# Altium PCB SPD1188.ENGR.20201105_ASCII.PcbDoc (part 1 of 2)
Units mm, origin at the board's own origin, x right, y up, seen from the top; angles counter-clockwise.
Board outline 110.11 x 115.1 mm, 2 copper layers (Top Layer, Bottom Layer); 167 components, 110 nets, 467 pads, 496 vias.
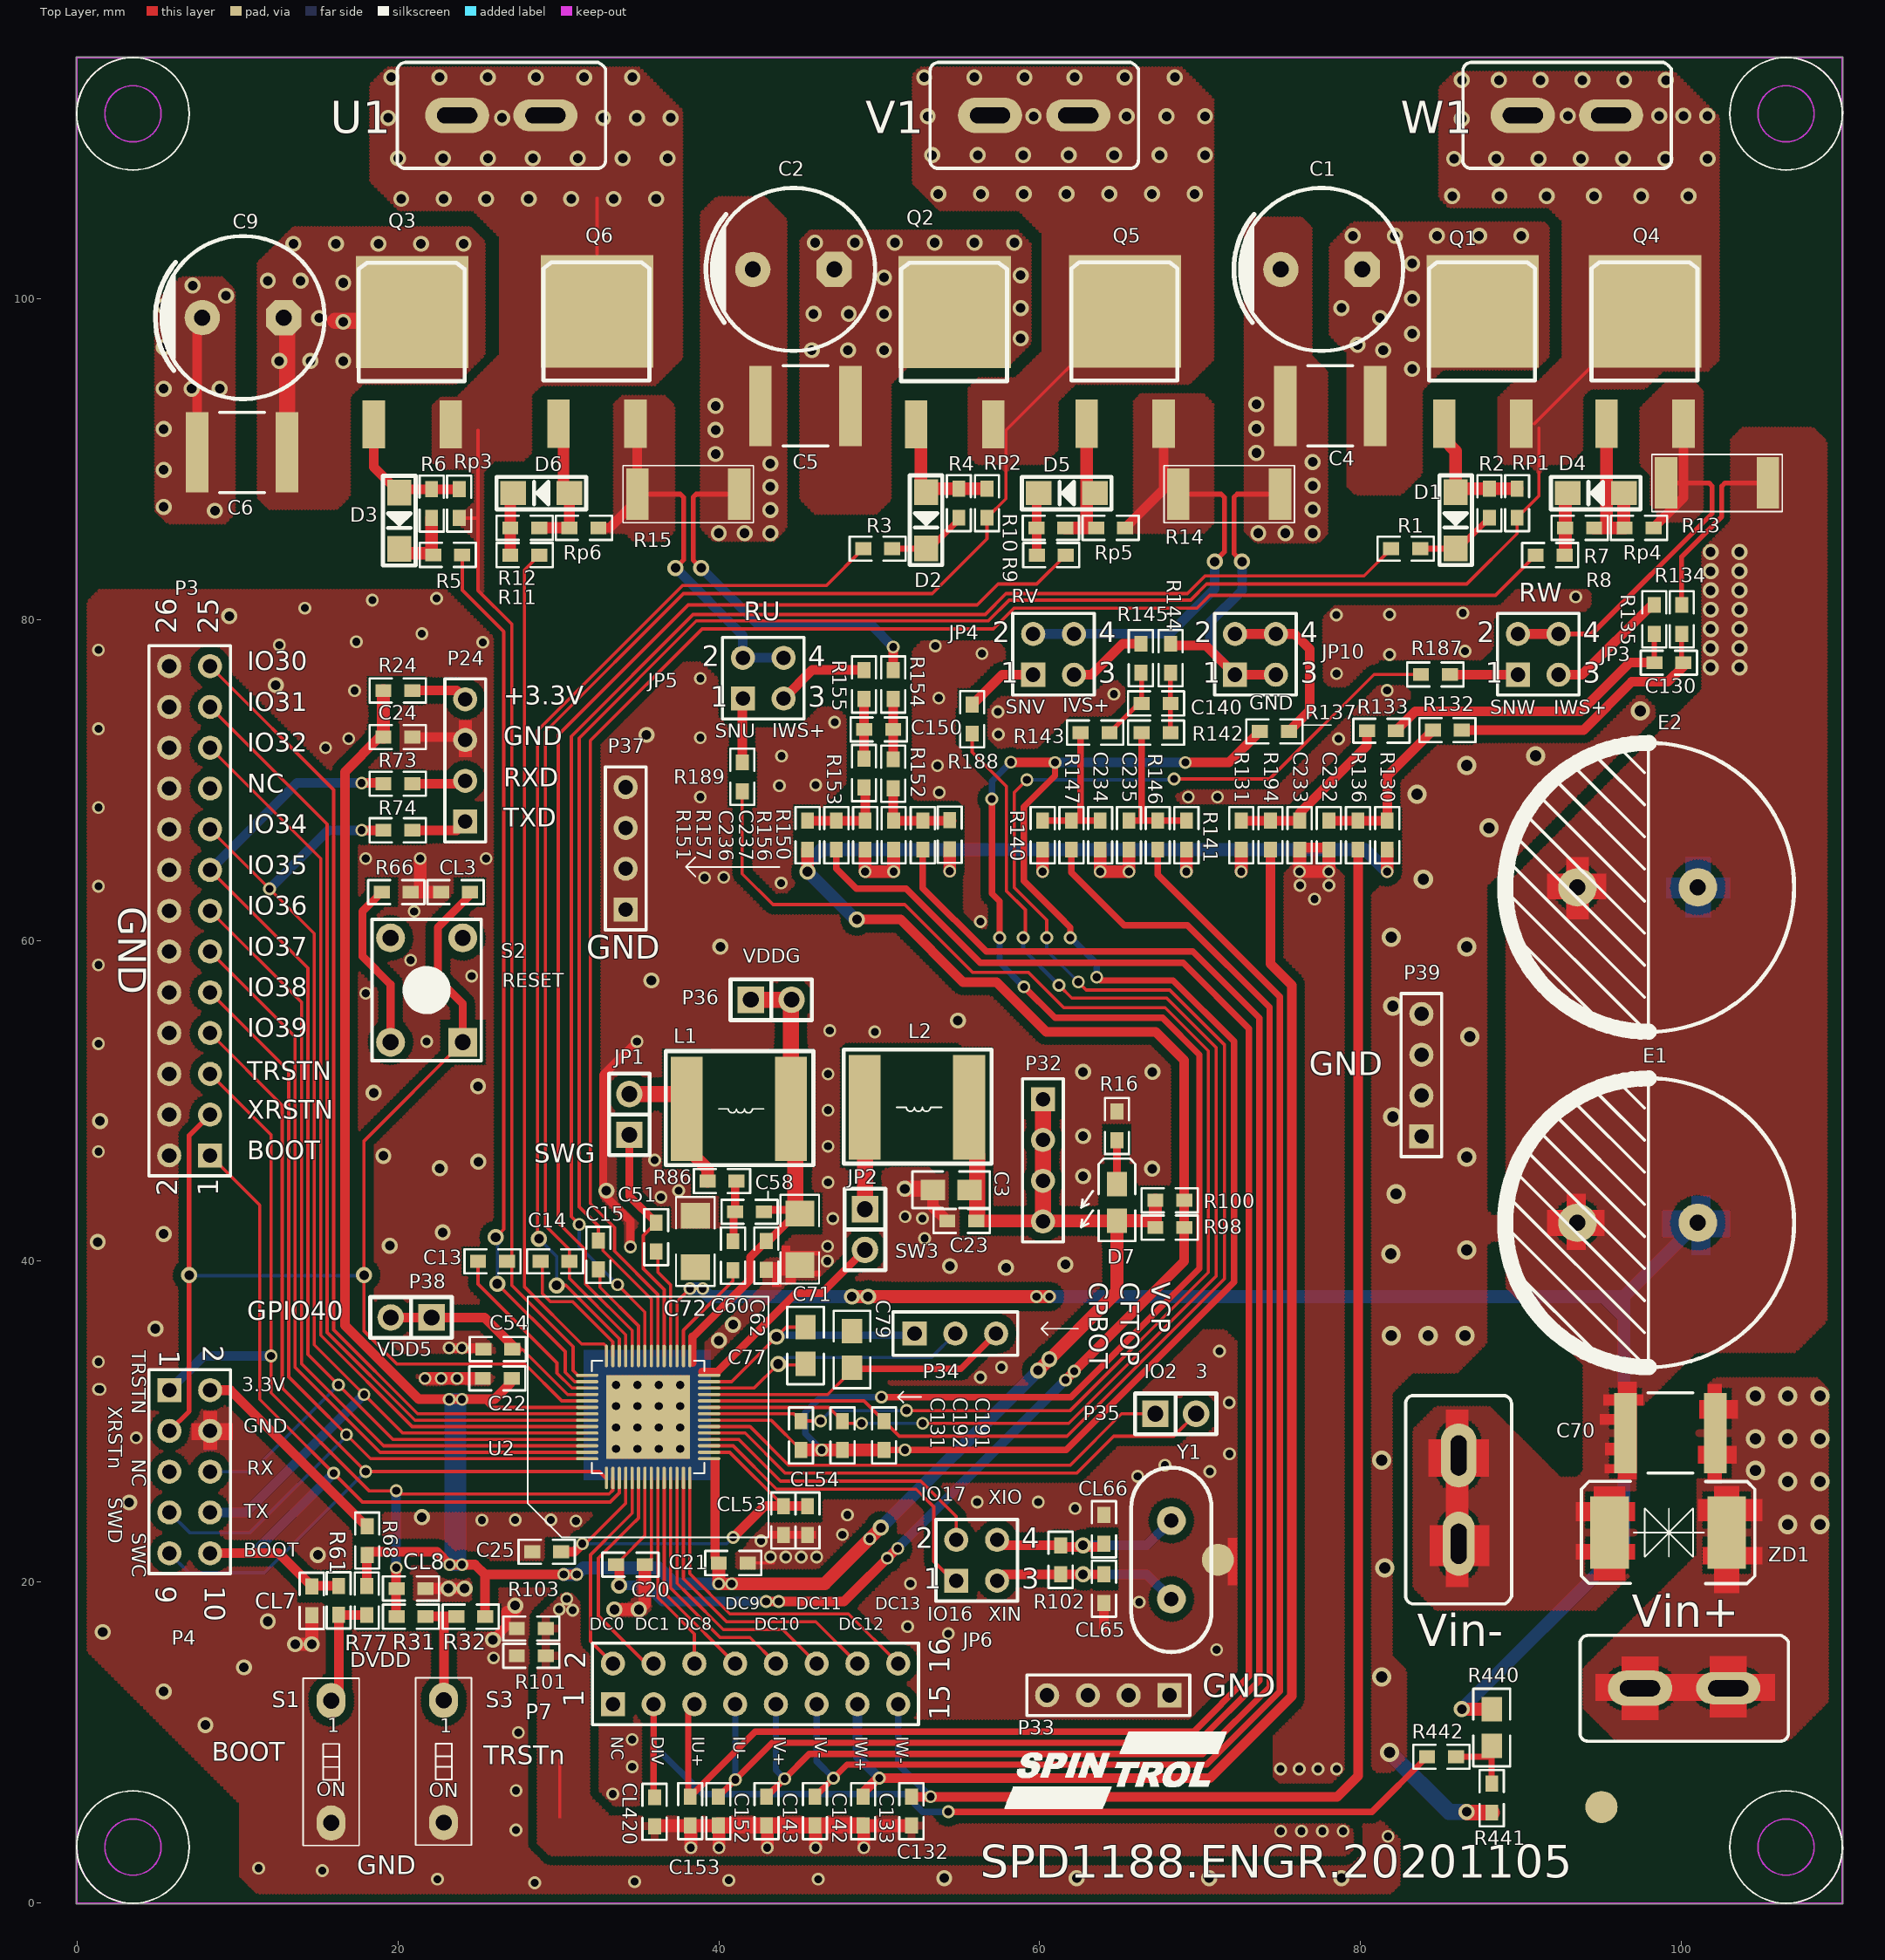
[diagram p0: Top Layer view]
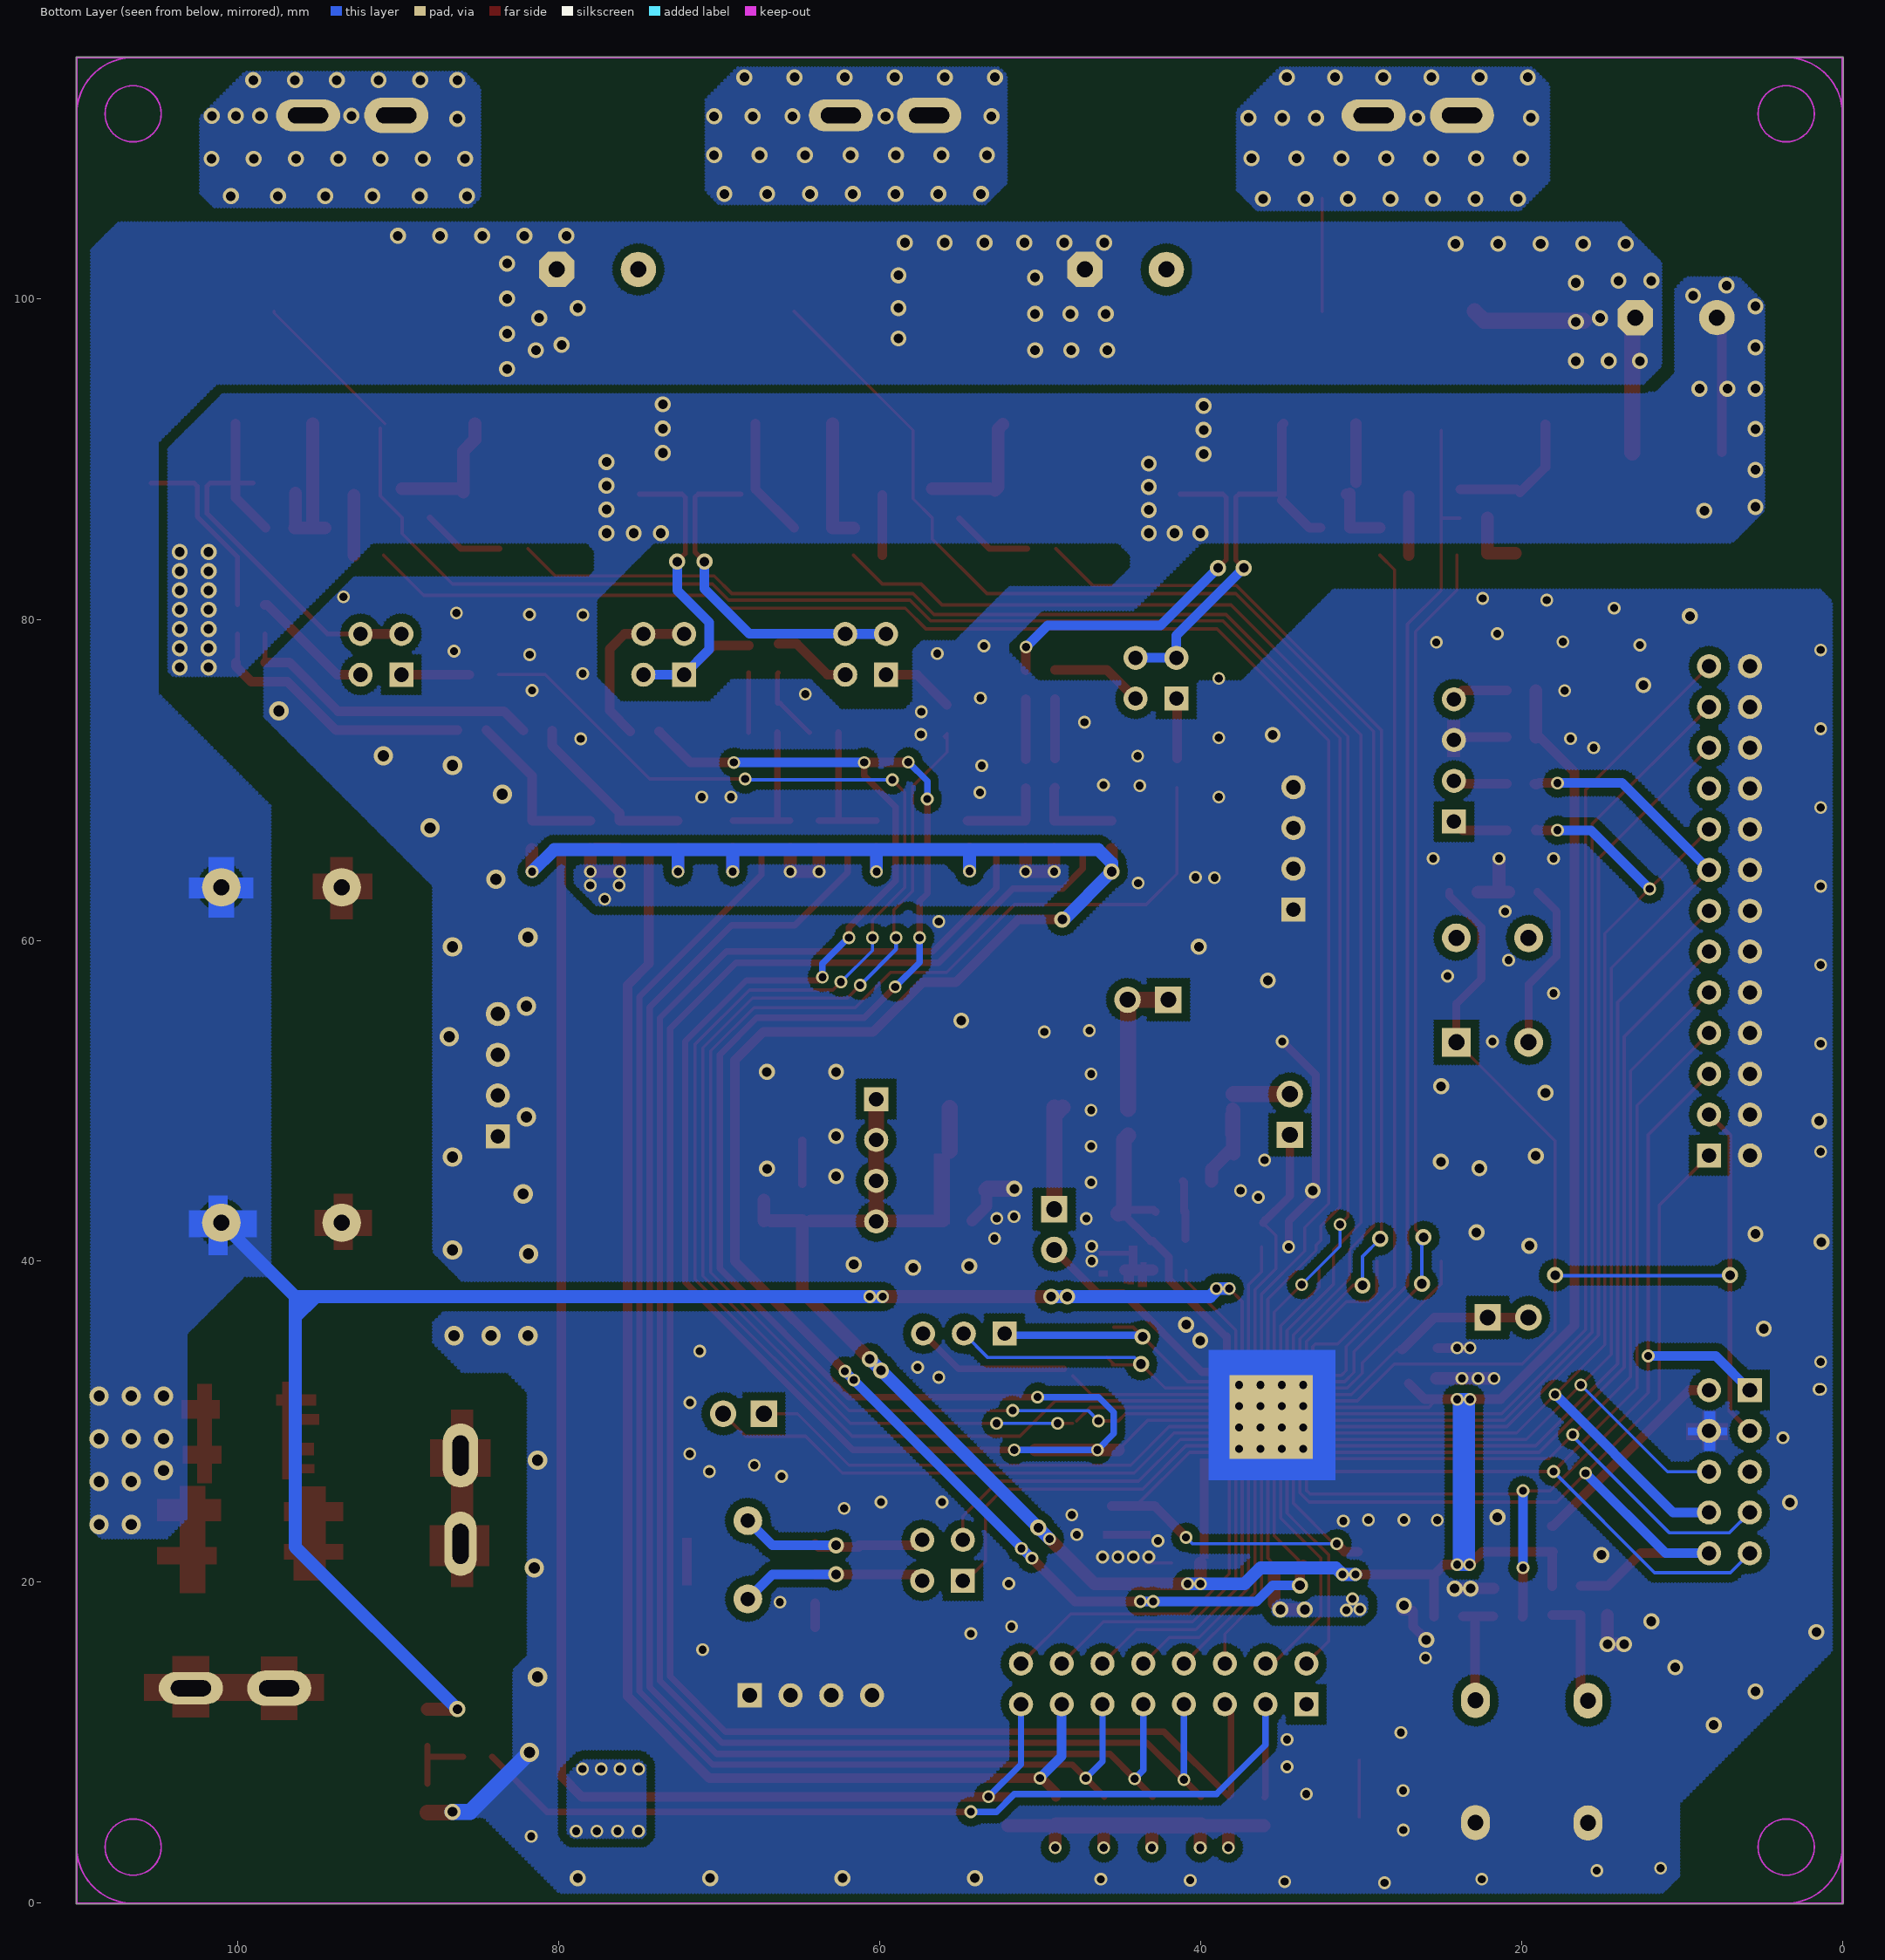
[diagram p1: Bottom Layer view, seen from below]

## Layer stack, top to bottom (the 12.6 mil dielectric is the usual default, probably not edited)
Top Solder: solder mask 0.0102, Solder Resist, Dk 3.5
Top Layer: signal copper 0.0356
Dielectric1: dielectric 0.32, FR-4, Dk 4.8
Bottom Layer: signal copper 0.0356
Bottom Solder: solder mask 0.0102, Solder Resist, Dk 3.5

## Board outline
-0.05,0 ccw(c0,0) 0,-0.05 110,-0.05 ccw(c110,0) 110.05,0 110.05,3.234 ccw(c106.51,3.5) 110.06,3.5 ccw(c110.01,3.5) 110.05,3.53 110.05,111.47 ccw(c110.01,111.5) 110.06,111.5 ccw(c106.51,111.5) 110.05,111.766 110.05,115 ccw(c110,115) 110,115.05 0,115.05 ccw(c0,115) -0.05,115

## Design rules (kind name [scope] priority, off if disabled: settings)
AssemblyTestPointUsage [All] p0: scope1count=1 scope1_0_kind=Board scope1_0_value=Board scope2count=1 scope2_0_kind=Board scope2_0_value=Board commentlength=0
AssemblyTestpoint [All] p0: scope1count=1 scope1_0_kind=Board scope1_0_value=Board scope2count=1 scope2_0_kind=Board scope2_0_value=Board commentlength=0
Clearance poly [All] p0 off: scope1count=1 scope1_0_kind=Board scope1_0_value=Board scope2count=1 scope2_0_kind=Board scope2_0_value=Board commentlength=48 gap=0.5 // Protel DXP Scope 1 Expression Was: InPolygon
Clearance VBAT [All] p0 off: scope1count=1 scope1_0_kind=Net scope1_0_value=VBAT scope2count=1 scope2_0_kind=Board scope2_0_value=Board commentlength=0 gap=0.9
Clearance [All] p0 off: scope1count=1 scope1_0_kind=Board scope1_0_value=Board scope2count=1 scope2_0_kind=Footprint scope2_0_value=OSC commentlength=60 gap=1.2 // Protel DXP Scope 1 Expression Was: InNamedPolygon('OSC')
Clearance all [All] p0: scope1count=1 scope1_0_kind=Board scope1_0_value=Board scope2count=1 scope2_0_kind=Board scope2_0_value=Board commentlength=0 gap=0.2
Clearance VBAT [InNet('VBAT')] p1 off: gap=0.9 ignorepadtopadclearanceinfootprint=FALSE except(0: Arc-Hole Track-Hole SMDPad-Hole THPad-Hole Via-Hole Fill-Hole Poly-Hole Region-Hole Text-Hole)
Clearance poly [InPolygon] p2: gap=0.5 ignorepadtopadclearanceinfootprint=FALSE except(0: Arc-Hole Track-Hole SMDPad-Hole THPad-Hole Via-Hole Fill-Hole Poly-Hole Region-Hole Text-Hole)
Clearance all [All] p3: gap=0.2 ignorepadtopadclearanceinfootprint=FALSE except(0: Arc-Hole Track-Hole SMDPad-Hole THPad-Hole Via-Hole Fill-Hole Poly-Hole Region-Hole Text-Hole)
Clearance [InNamedPolygon('OSC') vs HasFootprint('OSC')] p4: gap=1.2 ignorepadtopadclearanceinfootprint=FALSE except(0: Arc-Hole Track-Hole SMDPad-Hole THPad-Hole Via-Hole Fill-Hole Poly-Hole Region-Hole Text-Hole)
ComponentClearance [All] p0 off: scope1count=1 scope1_0_kind=Board scope1_0_value=Board scope2count=1 scope2_0_kind=Board scope2_0_value=Board commentlength=0 gap=0.254 collisioncheckmode=3
ComponentClearance [All] p1 off: gap=0.254 collisioncheckmode=3 verticalgap=0.254 showdistances=FALSE
DiffPairsRouting [All] p0: scope1count=1 scope1_0_kind=Board scope1_0_value=Board scope2count=1 scope2_0_kind=Board scope2_0_value=Board commentlength=0
DiffPairsRouting [All] p1: maxlimit=1 minlimit=0.2 mostfreqgap=0.2 toplayer_minwidth=0.381 toplayer_maxwidth=0.381 toplayer_prefwidth=0.381 bottomlayer_minwidth=0.381 bottomlayer_maxwidth=0.381 bottomlayer_prefwidth=0.381 maxuncoupledlength=12.7
FabricationTestPointUsage [All] p0: scope1count=1 scope1_0_kind=Board scope1_0_value=Board scope2count=1 scope2_0_kind=Board scope2_0_value=Board commentlength=0 valid=0 allowmultiple=FALSE
FabricationTestpoint [All] p0: scope1count=1 scope1_0_kind=Board scope1_0_value=Board scope2count=1 scope2_0_kind=Board scope2_0_value=Board commentlength=0 side=3 testpointundercomponent=TRUE minsize=1.016 maxsize=2.54 preferedsize=1.524 minholesize=0 maxholesize=1.016 preferedholesize=0.813 testpointgrid=0.025
FanoutControl Fanout_BGA [All] p0 off: scope1count=1 scope1_0_kind=Board scope1_0_value=Board scope2count=1 scope2_0_kind=Board scope2_0_value=Board commentlength=69 // Protel DXP Scope 1 Expression Was: IsBGA   Fanout_BGA (Default Rule)
FanoutControl Fanout_LCC [All] p0 off: scope1count=1 scope1_0_kind=Board scope1_0_value=Board scope2count=1 scope2_0_kind=Board scope2_0_value=Board commentlength=69 // Protel DXP Scope 1 Expression Was: IsLCC   Fanout_LCC (Default Rule)
FanoutControl Fanout_SOIC [All] p0 off: scope1count=1 scope1_0_kind=Board scope1_0_value=Board scope2count=1 scope2_0_kind=Board scope2_0_value=Board commentlength=71 // Protel DXP Scope 1 Expression Was: IsSOIC   Fanout_SOIC (Default Rule)
FanoutControl Fanout_Small [All] p0 off: scope1count=1 scope1_0_kind=Board scope1_0_value=Board scope2count=1 scope2_0_kind=Board scope2_0_value=Board commentlength=84 // Protel DXP Scope 1 Expression Was: (CompPinCount < 5)   Fanout_Small (Default Rule)
FanoutControl Fanout_Default [All] p0: scope1count=1 scope1_0_kind=Board scope1_0_value=Board scope2count=1 scope2_0_kind=Board scope2_0_value=Board commentlength=30 // Fanout_Default (Default Rule)
FanoutControl Fanout_Small [All] p1 off: bgadir=Out bgaviamode=Centered fanoutstyle=Auto fanoutdirection=Alternating viagrid=0.025 // Protel DXP Scope 1 Expression Was: (CompPinCount < 5)   Fanout_Small (Default Rule)
FanoutControl Fanout_Default [All] p2: bgadir=Out bgaviamode=Centered fanoutstyle=Auto fanoutdirection=Alternating viagrid=0.025 // Fanout_Default (Default Rule)
FanoutControl Fanout_SOIC [All] p3 off: bgadir=Out bgaviamode=Centered fanoutstyle=Auto fanoutdirection=Alternating viagrid=0.025 // Protel DXP Scope 1 Expression Was: IsSOIC   Fanout_SOIC (Default Rule)
FanoutControl Fanout_BGA [All] p4 off: bgadir=Out bgaviamode=Centered fanoutstyle=Auto fanoutdirection=Alternating viagrid=0.025 // Protel DXP Scope 1 Expression Was: IsBGA   Fanout_BGA (Default Rule)
FanoutControl Fanout_LCC [All] p5 off: bgadir=Out bgaviamode=Centered fanoutstyle=Auto fanoutdirection=Alternating viagrid=0.025 // Protel DXP Scope 1 Expression Was: IsLCC   Fanout_LCC (Default Rule)
Height [All] p0 off: scope1count=1 scope1_0_kind=Board scope1_0_value=Board scope2count=1 scope2_0_kind=Board scope2_0_value=Board commentlength=0
Height [All] p1 off: minheight=0 maxheight=25.4 prefheight=12.7
HoleSize [All] p0: scope1count=1 scope1_0_kind=Board scope1_0_value=Board scope2count=1 scope2_0_kind=Board scope2_0_value=Board commentlength=0 absolutevalues=TRUE maxlimit=5 minlimit=0.025 maxpercent=80.000 minpercent=20.000
HoleSize [All] p1: absolutevalues=TRUE maxlimit=5 minlimit=0.025 maxpercent=80.000 minpercent=20.000
HoleToHoleClearance [All] p0: scope1count=1 scope1_0_kind=Board scope1_0_value=Board scope2count=1 scope2_0_kind=Board scope2_0_value=Board commentlength=0
HoleToHoleClearance [All] p1: gap=0 allowstackedmicrovias=FALSE
LayerPairs [All] p0: scope1count=1 scope1_0_kind=Board scope1_0_value=Board scope2count=1 scope2_0_kind=Board scope2_0_value=Board commentlength=0 enforce=TRUE
MinimumSolderMaskSliver [All] p0: scope1count=1 scope1_0_kind=Board scope1_0_value=Board scope2count=1 scope2_0_kind=Board scope2_0_value=Board commentlength=0
MinimumSolderMaskSliver [All] p1: minsoldermaskwidth=0
NetAntennae [All] p0: scope1count=1 scope1_0_kind=Board scope1_0_value=Board scope2count=1 scope2_0_kind=Board scope2_0_value=Board commentlength=0
PasteMaskExpansion [All] p0: scope1count=1 scope1_0_kind=Board scope1_0_value=Board scope2count=1 scope2_0_kind=Board scope2_0_value=Board commentlength=0 expansion=0
PlaneClearance [All] p0 off: scope1count=1 scope1_0_kind=Board scope1_0_value=Board scope2count=1 scope2_0_kind=Board scope2_0_value=Board commentlength=0 clearance=0.508
PlaneClearance [All] p1 off: clearance=0.508
PlaneConnect [All] p0 off: scope1count=1 scope1_0_kind=Board scope1_0_value=Board scope2count=1 scope2_0_kind=Board scope2_0_value=Board commentlength=0 planeconnectstyle=Direct reliefexpansion=0.2 reliefentries=4 reliefconductorwidth=0.5 reliefairgap=0.2
PlaneConnect [All] p1 off: planeconnectstyle=Direct reliefexpansion=0.2 reliefentries=4 reliefconductorwidth=0.5 reliefairgap=0.2
PolygonConnect PolygonConnect_1 [All] p0: scope1count=1 scope1_0_kind=Board scope1_0_value=Board scope2count=1 scope2_0_kind=Board scope2_0_value=Board commentlength=0 connectstyle=Direct reliefconductorwidth=0.5 reliefentries=4 polygonreliefangle="90 Angle"
PolygonConnect via [All] p0 off: scope1count=1 scope1_0_kind=Board scope1_0_value=Board scope2count=1 scope2_0_kind=Board scope2_0_value=Board commentlength=48 connectstyle=Direct reliefconductorwidth=0.5 reliefentries=4 polygonreliefangle="45 Angle" // Protel DXP Scope 2 Expression Was: ispolygon
PolygonConnect via [isvia vs ispolygon] p1: connectstyle=Direct reliefconductorwidth=0.5 reliefentries=4 polygonreliefangle="45 Angle" airgapwidth=0.3
PolygonConnect PolygonConnect_1 [All] p2: connectstyle=Direct reliefconductorwidth=0.5 reliefentries=4 polygonreliefangle="90 Angle" airgapwidth=0.3
RoutingCorners [All] p0: scope1count=1 scope1_0_kind=Board scope1_0_value=Board scope2count=1 scope2_0_kind=Board scope2_0_value=Board commentlength=0 cornerstyle=45-Degree minsetback=2.54 maxsetback=2.54
RoutingLayers [All] p0: scope1count=1 scope1_0_kind=Board scope1_0_value=Board scope2count=1 scope2_0_kind=Board scope2_0_value=Board commentlength=0 top layer=Automatic bottom layer=Automatic
RoutingPriority [All] p1: routingpriority=4
RoutingPriority [All] p4: scope1count=1 scope1_0_kind=Board scope1_0_value=Board scope2count=1 scope2_0_kind=Board scope2_0_value=Board commentlength=0
RoutingTopology [All] p0: scope1count=1 scope1_0_kind=Board scope1_0_value=Board scope2count=1 scope2_0_kind=Board scope2_0_value=Board commentlength=0 topology=Shortest
RoutingVias [All] p0: scope1count=1 scope1_0_kind=Board scope1_0_value=Board scope2count=1 scope2_0_kind=Board scope2_0_value=Board commentlength=0 holewidth=0.4 width=0.8 viastyle="Through Hole" minholewidth=0.1 minwidth=0.3 maxholewidth=5 maxwidth=5
RoutingVias [All] p1: holewidth=0.4 width=0.8 viastyle="Through Hole" minholewidth=0.1 minwidth=0.3 maxholewidth=5 maxwidth=5
ShortCircuit [All] p0: scope1count=1 scope1_0_kind=Board scope1_0_value=Board scope2count=1 scope2_0_kind=Board scope2_0_value=Board commentlength=0 allowed=FALSE
SilkToBoardRegionClearance [All] p0: scope1count=1 scope1_0_kind=Board scope1_0_value=Board scope2count=1 scope2_0_kind=Board scope2_0_value=Board commentlength=0
SilkToSilkClearance [All] p0: scope1count=1 scope1_0_kind=Board scope1_0_value=Board scope2count=1 scope2_0_kind=Board scope2_0_value=Board commentlength=0
SilkToSilkClearance [All] p1: silktosilkclearance=0
SilkToSolderMaskClearance SilkscreenOverComponentPads [All] p0 off: scope1count=1 scope1_0_kind=Board scope1_0_value=Board scope2count=1 scope2_0_kind=Board scope2_0_value=Board commentlength=44 // Protel DXP Scope 1 Expression Was: IsPad
SilkToSolderMaskClearance SilkscreenOverComponentPads [IsPad] p1: minsilkscreentomaskgap=0 clearancetoexposedcopper=TRUE
SolderMaskExpansion [All] p0: scope1count=1 scope1_0_kind=Board scope1_0_value=Board scope2count=1 scope2_0_kind=Board scope2_0_value=Board commentlength=0 expansion=0.102
SolderMaskExpansion [All] p1: expansion=0.102 istentingtop=FALSE
UnRoutedNet [All] p0: scope1count=1 scope1_0_kind=Board scope1_0_value=Board scope2count=1 scope2_0_kind=Board scope2_0_value=Board commentlength=0
UnpouredPolygon [All] p0: scope1count=1 scope1_0_kind=Board scope1_0_value=Board scope2count=1 scope2_0_kind=Board scope2_0_value=Board commentlength=0
Width [All] p0: scope1count=1 scope1_0_kind=Board scope1_0_value=Board scope2count=1 scope2_0_kind=Board scope2_0_value=Board commentlength=0 maxlimit=5 minlimit=0.2 preferedwidth=0.2
Width [All] p1: maxlimit=5 minlimit=0.2 preferedwidth=0.2 minimp=50.000000 maximp=50.000000 favimp=50.000000
14 further rules are at their usual default settings.

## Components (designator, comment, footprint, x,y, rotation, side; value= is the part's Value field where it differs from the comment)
C1 "47uF/160V" RB5.0/10 80.1,101.8 r0 top
C2 "47uF/160V" RB5.0/10 47.2,101.8 r0 top
C3 "10uF/10V" 0805 54.476,44.451 r0 top
C4 "2.2uF/200V" 2220#1 78.1,93.3 r180 top
C5 "2.2uF/200V" 2220#1 45.4,93.3 r180 top
C6 "2.2uF/200V" 2220#1 10.3,90.4 r180 top
C9 "47uF/160V" RB5.0/10 12.9,98.8 r0 top
C13 "100nF/50V" 0603 25.9,40 r0 top
C14 "100nF/50V" 0603 29.8,40 r0 top
C15 "100nF/50V" 0603 32.5,40.4 r90 top
C20 "100nF/50V" 0603 34.5,21.1 r180 top
C21 "100nF/50V" 0603 40.9,21.2 r180 top
C22 "100nF/50V" 0603 26.2,32.7 r0 top
C23 "100nF/50V" 0603 55.139,42.51 r0 top
C24 "100nF/50V" 0603 20,72.662 r180 top
C25 "100nF/50V" 0603 29.28,21.9 r0 top
C51 "10nF/35V" 0603 36.1,41.5 r270 top
C54 "2.2UF/10V" 0603 26.23,34.53 r0 top
C58 "470pF±10%" 0603 41.92,43.08 r0 top
C60 "10nF/35V" 0603 40.89,40.35 r270 top
C62 "100nF/50V" 0603 42.96,40.36 r90 top
C70 "2.2uF/200V" 2220#2 99.3,29.3 r180 top
C71 "10uF/35V" 1206 44.99,42.93 r270 top
C72 "100nF/200V" 1206 38.6,39.68 r90 top
C77 "22nF/100V" 0805 45.41,34.75 r90 top
C79 "2.2uF/25V" 0805 48.3,34.5 r90 top
C130 "1nF" 0603 99.2,77.3 r0 top
C131 "100nF" 0603 45.12,29.15 r270 top
C132 "22pF" 0603 52.005,5.74 r270 top
C133 "22pF" 0603 48.996,5.74 r270 top
C140 "1nF" 0603 67.25,74.76 r0 top
C142 "22pF" 0603 45.987,5.74 r270 top
C143 "22pF" 0603 42.979,5.74 r270 top
C150 "1nF" 0603 49.97,73.14 r0 top
C152 "22pF" 0603 39.97,5.74 r270 top
C153 "22pF" 0603 38.215,5.74 r270 top
C191 "100nF" 0603 50.3,29.15 r270 top
C192 "100nF" 0603 47.71,29.15 r270 top
C232 "22pF" 0603 78.011,66.55 r270 top
C233 "22pF" 0603 76.192,66.55 r90 top
C234 "22pF" 0603 63.766,66.55 r270 top
C235 "22pF" 0603 65.558,66.55 r90 top
C236 "22pF" 0603 50.896,66.55 r270 top
C237 "22pF" 0603 49.123,66.55 r90 top
CL3 "1uF/16V" 0603 23.6,63 r0 top
CL7 "100nF" 0603 14.64,18.84 r270 top
CL8 "100nF" 0603 20.823,19.61 r0 top
CL53 "10nF/35V" 0603 44.03,23.85 r90 top
CL54 "2.2uF/10V" 0603 45.53,23.85 r90 top
CL65 "CAP CER 20PF 10V" 0603 64,19.6 r90 top
CL66 "CAP CER 20PF 10V" 0603 64,23.3 r270 top
CL420 "1nF" 0603 36,5.7 r90 top
D1 "IN4148W-E3-08" LL-34 85.916,86.167 r90 top
D2 "IN4148W-E3-08" LL-34 52.916,86.167 r90 top
D3 "IN4148W-E3-08" LL-34 20.094,86.142 r90 top
D4 "IN4148W-E3-08" LL-34 94.633,87.863 r0 top
D5 "IN4148W-E3-08" LL-34 61.677,87.863 r0 top
D6 "IN4148W-E3-08" LL-34 28.935,87.863 r0 top
D7 "LED2" LED0805 64.81,43.67 r90 top
E1 "470uF/160V" 470uF_100V 98,42.4 r0 top locked
E2 "470uF/160V" 470uF_100V 98,63.3 r0 top locked
JP1 "2.54*2" CON2 34.43,47.88 r180 top
JP2 "Jumper" CON2 49.11,43.25 r0 top
JP3 "Header 2X2" HDR2X2 89.79,76.55 r0 top
JP4 "Header 2X2" HDR2X2 59.59,76.55 r0 top
JP5 "Header 2X2" HDR2X2 41.5,75.06 r0 top
JP6 "Header 2X2" HDR2X2 54.8,20.1 r0 top
JP10 "Header 2X2" HDR2X2 72.17,76.55 r0 top
L1 "CD105-470K" CD105 38,49.5 r270 top
L2 "10uH" CD105 49.09,49.59 r270 top
P3 "双排插针2.54*13" HDR2X13 8.3,46.6 r90 top
P4 "双排插针2.54*5" HDR2X5 5.77,31.97 r270 top
P7 "双排插针2.54*8" HDR2X8 33.4,12.4 r0 top locked
P24 "2.54mm母座" HDR1X4 24.2,67.4 r90 top
P32 "2.54*4" HDR1X4 60.2,50.1 r270 top
P33 "2.54*4" HDR1X4 68.08,12.96 r180 top
P34 "2.54*3插针" 2.54*3 52.2,35.5 r0 top
P35 "2.54*2" CON2 67.2,30.5 r90 top
P36 "2.54*2" CON2 42,56.3 r90 top
P37 "2.54*4" HDR1X4 34.2,61.92 r90 top
P38 "2.54*2" CON2 22.1,36.5 r270 top
P39 "2.54*4" HDR1X4 83.78,47.79 r90 top
Q1 "NCE1540K" TO-252 87.6,95.94 r0 top
Q2 "NCE1540K" TO-252 54.7,95.9 r0 top
Q3 "NCE1540K" TO-252 20.9,95.9 r0 top
Q4 "NCE1540K" TO-252 97.716,95.94 r0 top
Q5 "NCE1540K" TO-252 65.316,95.94 r0 top
Q6 "NCE1540K  150V/29A" TO-252 32.416,95.94 r0 top
R1 "22R" 0603 82.8,84.4 r0 top
R2 "22R" 0603 88.016,87.235 r90 top
R3 "22R" 0603 49.9,84.4 r0 top
R4 "22R" 0603 54.956,87.235 r90 top
R5 "22R" 0603 23.116,84.015 r180 top
R6 "22R" 0603 22.11,87.21 r90 top
R7 "22R" 0603 91.8,84 r0 top
R8 "22R" 0603 93.641,85.7 r0 top
R9 "22R" 0603 60.716,84 r180 top
R10 "22R" 0603 60.693,85.7 r0 top
R11 "22R" 0603 27.91,84 r180 top
R12 "22R" 0603 27.91,85.7 r0 top
R13 "0.005R /3W 1% 50ppm" 2512 102.2,88.5 r180 top
R14 "0.005R /3W 1% 50ppm" 2512 71.8,87.8 r180 top
R15 "0.005R /3W 1% 50ppm" 2512 38.1,87.8 r180 top
R16 "1k" 0603 64.81,48.43 r270 top
R24 "0R" 0603 20,75.565 r180 top
R31 "2K" 0603 20.823,17.86 r0 top
R32 "3K" 0603 24.546,17.86 r180 top
R61 "2K" 0603 16.32,18.87 r270 top
R66 "22R" 0603 19.9,63 r0 top
R68 "0R" 0603 18.1,22.6 r270 top
R73 "RES SMD 0.0OHM" 0603 20,69.758 r180 top
R74 "RES SMD 0.0OHM" 0603 20,66.855 r180 top
R77 "3K" 0603 18.07,18.86 r270 top
R86 "470k" 0603 40.2,45 r180 top
R98 "RES SMD 0.0OHM" 0603 68.1,42.1 r180 top
R100 "RES SMD 0.0OHM" 0603 68.1,43.8 r180 top
R101 "RES SMD 0.0OHM" 0603 28.32,15.42 r0 top
R102 "NI" 0603 61.3,21.4 r90 top
R103 "RES SMD 0.0OHM" 0603 28.32,17.12 r0 top
R130 "2K" 0603 81.65,66.55 r270 top
R131 "2K" 0603 72.554,66.55 r270 top
R132 "2K" 0603 85.4,73.1 r180 top
R133 "2K" 0603 81.29,73.06 r180 top
R134 "1R" 0603 100,80 r270 top
R135 "1R" 0603 98.29,80 r270 top
R136 "2K" 0603 79.831,66.55 r270 top
R137 "1" 0603 74.62,73.02 r180 top
R140 "2K" 0603 60.184,66.55 r90 top
R141 "2K" 0603 69.14,66.55 r270 top
R142 "2K" 0603 67.25,72.94 r180 top
R143 "2K" 0603 63.45,72.94 r180 top
R144 "1R" 0603 68.15,77.58 r270 top
R145 "1R" 0603 66.3,77.58 r270 top
R146 "2K" 0603 67.349,66.55 r270 top
R147 "2K" 0603 61.975,66.55 r270 top
R150 "2K" 0603 54.39,66.58 r270 top
R151 "2K" 0603 45.535,66.55 r270 top
R152 "2K" 0603 50.87,70.38 r270 top
R153 "2K" 0603 49.05,70.42 r270 top
R154 "1R" 0603 50.87,75.94 r270 top
R155 "1R" 0603 49.05,75.94 r270 top
R156 "2K" 0603 52.712,66.55 r270 top
R157 "2K" 0603 47.329,66.55 r270 top
R187 "1" 0603 84.65,76.56 r180 top
R188 "1" 0603 55.79,73.78 r270 top
R189 "1" 0603 41.47,70.19 r270 top
R194 "2K" 0603 74.373,66.55 r270 top
R440 "100k" 0805 88.16,10.95 r90 top
R441 "3k" 0603 88.16,6.55 r90 top
R442 "2K" 0603 85.03,9.13 r0 top (schematic designator R163)
RP1 "20K" 0603 89.741,87.235 r270 top
RP2 "20K" 0603 56.716,87.235 r270 top
Rp3 "20K" 0603 23.826,87.21 r270 top
Rp4 "20K" 0603 97.341,85.7 r0 top
Rp5 "20K" 0603 64.416,85.7 r0 top
Rp6 "20K" 0603 31.6,85.7 r0 top
S1 "DSIC01LH-P" S7.62*1 15.85,12.623 r270 top
S2 "SW-PB" SWITCH-4 21.8,56.9 r90 top
S3 "DSIC01LH-P" S7.62*1 22.86,12.643 r270 top
U1 "250插片" PIN_L 29.2,111.4 r180 top
U2 "SPD1188" QFN56L_20190222 35.6,30.3 r90 top locked
V1 "250插片" PIN_L 62.4,111.4 r180 top
Vin+ "250插片" PIN_L 102.9,13.4 r180 top
Vin- "250插片" PIN_L 86.1,22.4 r90 top
W1 "250插片" PIN_L 95.6,111.4 r180 top
Y1 "OSC32MHz" OSC 68.2,21.4 r90 top
ZD1 "1.5SMC91A" SMCTVS 95.5,23.1 r0 top

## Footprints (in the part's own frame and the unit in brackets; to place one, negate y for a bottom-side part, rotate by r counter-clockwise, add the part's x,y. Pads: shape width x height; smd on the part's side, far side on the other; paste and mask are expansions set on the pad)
2.54*3 [mm]
  rect 1.5x1.5 hole 0.9: 1(0,0)
  round 1.5 hole 0.9: 2(2.54,0) 3(5.08,0)
  silkscreen extent -1.35,-1.35 6.43,1.35
470uF_100V [mm] "470uF/100V_LAYOUT"
  round 2.4 hole 1: 1(3,0) 2(-4.5,0)
  silkscreen extent -9.12,-9 9,9.14
0603 [mm]
  rect 1x0.8 smd: 1(-0.9,0) 2(0.9,0)
  silkscreen extent -1.75,-0.75 1.75,0.75
0805 [mil]
  rect 60x50 smd: 1(-45,0) 2(45,0)
  silkscreen extent -95,-45 95,45
1206 [mm]
  rect 1.6x1.8 smd: 1(-0.042,0.058) 2(3.158,0.058)
  silkscreen extent -1.22,-1.14 4.32,1.26
2220#1 [mm] "Chip Capacitor, Body 5.7x5.0mm, IPC High Density"
  rect 1.4x5 smd: 1(-2.8,0) 2(2.8,0)
  silkscreen extent -1.4,-2.5 1.4,2.5
2220#2 [mm] "Chip Capacitor, Body 5.7x5.0mm, IPC High Density"
  rect 1.4x5 smd: 1(-2.8,0) 2(2.8,0)
  Mechanical 13 keep-out region: 34.601,-15.509 34.376,-15.509 34.376,-17.795 34.601,-17.795
  silkscreen extent -1.4,-2.5 1.4,2.5
2512 [mm]
  rect 1.4x3.2 smd: 1(-3.175,0) 2(3.175,0)
  silkscreen extent -4.06,-1.78 4.06,1.78
CD105 [mm]
  rect 6.5x2 smd: 1(0,0) 2(0,6.5)
  silkscreen extent -3.6,-1.3 3.5,7.9
CON2 [mil]
  rect 65x65 hole 39: 1(0,0)
  round 65 hole 39: 2(0,-100)
  silkscreen extent -50,-150 50,50
HDR1X4 [mm] "Connector; Header; 4 Position"
  rect 1.5x1.5 hole 0.9: 1(0,0)
  round 1.5 hole 0.9: 2(2.54,0) 3(5.08,0) 4(7.62,0)
  silkscreen extent -1.27,-1.27 8.89,1.27
HDR2X2 [mm] "Connector; Header; 2x2 Position"
  rect 1.5x1.5 hole 0.9: 1(0,0)
  round 1.5 hole 0.9: 2(0,2.54) 3(2.54,0) 4(2.54,2.54)
  silkscreen extent -1.27,-1.27 3.81,3.81
HDR2X5 [mm] "Connector; Header; 5x2 Position"
  rect 1.5x1.5 hole 0.9: 1(0,0)
  round 1.5 hole 0.9: 2(0,2.54) 3(2.54,0) 4(2.54,2.54) 5(5.08,0) 6(5.08,2.54) 7(7.62,0) 8(7.62,2.54) 9(10.16,0) 10(10.16,2.54)
  silkscreen extent -1.27,-1.27 11.43,3.81
HDR2X8 [mm] "Connector; Header; 8x2 Position"
  rect 1.5x1.5 hole 0.9: 1(0,0)
  round 1.5 hole 0.9: 2(0,2.54) 3(2.54,0) 4(2.54,2.54) 5(5.08,0) 6(5.08,2.54) 7(7.62,0) 8(7.62,2.54) 9(10.16,0) 10(10.16,2.54) 11(12.7,0) 12(12.7,2.54) 13(15.24,0) 14(15.24,2.54) 15(17.78,0) 16(17.78,2.54)
  silkscreen extent -1.27,-1.27 19.05,3.81
HDR2X13 [mm] "Connector; Header; 13x2 Position"
  rect 1.5x1.5 hole 0.9: 1(0,0)
  round 1.5 hole 0.9: 2(0,2.54) 3(2.54,0) 4(2.54,2.54) 5(5.08,0) 6(5.08,2.54) 7(7.62,0) 8(7.62,2.54) 9(10.16,0) 10(10.16,2.54) 11(12.7,0) 12(12.7,2.54) 13(15.24,0) 14(15.24,2.54) 15(17.78,0) 16(17.78,2.54) 17(20.32,0) 18(20.32,2.54) 19(22.86,0) 20(22.86,2.54) 21(25.4,0) 22(25.4,2.54) 23(27.94,0) 24(27.94,2.54) 25(30.48,0) 26(30.48,2.54)
  silkscreen extent -1.27,-1.27 31.75,3.81
LED0805 [mil]
  rect 60x50 smd: 1(-45,0) 2(45,0)
  silkscreen extent -95,-45 108,88
LL-34 [mm]
  rect 1.6x1.5 smd: 1(1.758,0) 2(-1.742,0)
  silkscreen extent -2.79,-1.02 2.8,1.02
OSC [mm] "CRYSTAL 32.0000MHZ 20PF T/H"
  round 1.8 hole 0.9: 1(-2.44,0) 2(2.44,0)
  silkscreen extent -5.75,-2.5 5.75,2.5
PIN_L [mm]
  oval 4x2 hole 1 slot 2.5 at 0 deg: 1(0,0)
  oval 4x2.2 hole 1 slot 2.5 at 0 deg: 1(5.5,0)
  silkscreen extent -3.75,-3.3 9.24,3.3
QFN56L_20190222 [mm]
  oval 1.4x0.2 smd: 1(-3.8,2.6) 2(-3.8,2.2) 3(-3.8,1.8) 4(-3.8,1.4) 5(-3.8,1) 6(-3.8,0.6) 7(-3.8,0.2) 8(-3.8,-0.2) 9(-3.8,-0.6) 10(-3.8,-1) 11(-3.8,-1.4) 12(-3.8,-1.8) 13(-3.8,-2.2) 14(-3.8,-2.6) 29(3.8,-2.6) 30(3.8,-2.2) 31(3.8,-1.8) 32(3.8,-1.4) 33(3.8,-1) 34(3.8,-0.6) 35(3.8,-0.2) 36(3.8,0.2) 37(3.8,0.6) 38(3.8,1) 39(3.8,1.4) 40(3.8,1.8) 41(3.8,2.2) 42(3.8,2.6)
  oval 0.2x1.4 smd: 15(-2.6,-3.8) 16(-2.2,-3.8) 17(-1.8,-3.8) 18(-1.4,-3.8) 19(-1,-3.8) 20(-0.6,-3.8) 21(-0.2,-3.8) 22(0.2,-3.8) 23(0.6,-3.8) 24(1,-3.8) 25(1.4,-3.8) 26(1.8,-3.8) 27(2.2,-3.8) 28(2.6,-3.8) 43(2.6,3.8) 44(2.2,3.8) 45(1.8,3.8) 46(1.4,3.8) 47(1,3.8) 48(0.6,3.8) 49(0.2,3.8) 50(-0.2,3.8) 51(-0.6,3.8) 52(-1,3.8) 53(-1.4,3.8) 54(-1.8,3.8) 55(-2.2,3.8) 56(-2.6,3.8)
  rect 5.2x5.2 smd: 57(0,0)
  rect 5.2x5.2 smd far side: 57(0,0)
  silkscreen extent -7.5,-7.5 7.5,7.5
RB5.0/10 [mm]
  oct 2.2x2.2 hole 1: 1(0,0)
  round 2.2 hole 1: 2(-5.08,0)
  silkscreen extent -8,-5.08 2.54,5.08
S7.62*1 [mm]
  oval 2.2x1.8 hole 1: 1(0,0) 2(7.62,0)
  silkscreen extent -1.4,-1.74 9.02,1.74
SMCTVS [mm]
  rect 2.4x4.5 smd: 1(7.3,0) 2(0,0)
  silkscreen extent -1.75,-3.18 9.05,3.18
SWITCH-4 [mm] "Switch; 4 Leads; Body 6 x 6 mm"
  rect 1.8x1.8 hole 1: 1(-3.25,-2.25)
  round 1.8 hole 1: 2(-3.25,2.25) 3(3.25,-2.25) 4(3.25,2.25)
  silkscreen extent -4.4,-3.4 4.4,3.4
TO-252 [mm]
  rect 1.4x3 smd: 1(-2.4,-3.75) 3(2.4,-3.75)
  rect 7x7 smd: 2(0,3.25)
  silkscreen extent -3.34,-1.06 3.26,6.31

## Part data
C1 C2 C9: library part "Cap Pol1", "Polarized Capacitor (Radial)"
C3 C4 C5 C6 C13 C14 C15 C20 C21 C22 C23 C24 C25 C51 C58 C60 C70 C71 C72 C77 C79 C130 C131 C132 C133 C140 C142 C143 C150 C152 C153 C191 C192 C232 C233 C234 C235 C236 C237: library part CAP, "Capacitor"
C54 CL54 CL420: library part "Capacitor Unpolarized", "CAP CER 2.2UF 10V X7R 0603"
C62: library part CAP, "AR02010135A0"
CL3: library part "Capacitor Unpolarized", "CAP CER 1UF 16V X7R 0603"
CL7 CL8: library part "Capacitor Unpolarized", "Unpolarized Capacitor"
CL53: library part "Capacitor Unpolarized", "CAP CER 10000PF 10V X7R 0603"
CL65 CL66: library part "Capacitor Unpolarized", "CAP CER 20PF 10V X7R 0603"
D1 D2 D3 D4 D5 D6: library part Diode, "Default Diode"
D7: "Typical RED, GREEN, YELLOW, AMBER GaAs LED"
E1 E2: library part CAP-EC, "100PX471MEFC16*25  rubycon"
JP1 P35 P36 P38: library part "Header 2", "Header, 2-Pin"
JP2: "Jumper Wire"
JP3 JP4 JP5 JP6 JP10: "Header, 2-Pin, Dual row"
L1 L2: library part "Inductor Iron", "Magnetic-Core Inductor"
P3: library part "Header 13X2", "Header, 13-Pin, Dual row"
P4: library part "Header 5X2", "Header, 5-Pin, Dual row"
P7: library part "Header 8X2", "Header, 8-Pin, Dual row"
P24 P32 P33 P37 P39: library part "Header 4", "Header, 4-Pin"
P34: library part "Header 3", "A9TS21-0011"
Q1 Q2 Q3 Q4 Q5 Q6: library part IRF1010E, "HEXFET Power MOSFET"
R1 R2 R3 R4 R5 R6 R7 R8 R9 R10 R11 R12 R86 R130 R131 R132 R133 R134 R135 R136 R137 R140 R141 R142 R143 R144 R145 R146 R147 R150 R151 R152 R153 R154 R155 R156 R157 R187 R188 R189 R194 R440 R441 R442 RP1 RP2 Rp3 Rp4 Rp5 Rp6: library part RES2
R13 R14 R15: library part RES1
R16: library part Res1, "Resistor"
R24 R68 R102: library part Resistor, "Resistor"
R31 R32 R61 R77: library part Resistor
R66: library part Resistor, "RES SMD 100 OHM 1% 1/10W"
R73 R74 R98 R100 R101 R103: library part Resistor, "RES SMD 0.0OHM JUMPER 1/10W"
S1 S3: library part SW-2
S2: "Switch Key"
U1 V1 W1: library part TP
U2: "32-bit MCU with  Motor Pre-driver and power"
Vin+ Vin-: library part PAD, "TE"
Y1: "CRYSTAL 32.0000MHZ 20PF T/H"
ZD1: library part TVS

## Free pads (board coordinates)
  round 2 smd: 0(71.1,21.4) 1(95,6)

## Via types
v1: diameter 0.8, hole 0.5, Top Layer to Bottom Layer, tented both sides, 215 vias
v2: diameter 1, hole 0.6, Top Layer to Bottom Layer, 161 vias
v3: diameter 1, hole 0.6, Top Layer to Bottom Layer, tented both sides, 71 vias
v4: diameter 1.2, hole 0.7, Top Layer to Bottom Layer, tented both sides, 33 vias
v5: diameter 0.8, hole 0.5, Top Layer to Bottom Layer, 16 vias

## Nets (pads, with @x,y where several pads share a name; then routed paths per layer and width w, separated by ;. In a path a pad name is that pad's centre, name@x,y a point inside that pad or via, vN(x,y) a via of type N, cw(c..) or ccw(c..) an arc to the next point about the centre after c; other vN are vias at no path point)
ADC0: P7.2 U2.5 | length 13.2
  Top Layer w0.2: P7.2@33.4,14.94 32.01,16.33 32.01,21.71 33.905,23.605 34.6,24.3 U2.5@34.6,26.5
ADC1: P7.4 U2.6 | length 14.3
  Top Layer w0.2: U2.6@35,26.5 35,24 34.515,23.515 32.5,21.5 32.5,17.9 35.46,14.94 P7.4@35.94,14.94
ADC8: P7.6 U2.9 | length 12.5
  Top Layer w0.2: U2.9@36.2,26.5 36.2,19.058 36.909,18.349 38.48,16.778 P7.6@38.48,14.94
ADC9: P7.8 U2.10 | length 13.4
  Top Layer w0.2: U2.10@36.6,26.5 36.6,19.351 37.241,18.711 41.011,14.94 P7.8@41.02,14.94
ADC10: P7.10 U2.11 | length 15.4
  Top Layer w0.2: U2.11@37,26.5 37,19.644 37.637,19.007 40.084,16.56 41.94,16.56 P7.10@43.56,14.94
ADC11: P7.12 U2.12 | length 17.3
  Top Layer w0.2: U2.12@37.4,26.5 37.4,19.937 38.099,19.239 40.287,17.05 43.99,17.05 P7.12@46.1,14.94
ADC12: P7.14 U2.13 | length 19.3
  Top Layer w0.2: U2.13@37.8,26.5 37.8,20.23 38.585,19.445 40.49,17.54 46.04,17.54 P7.14@48.64,14.94
ADC13: P7.16 U2.14 | length 21.3
  Top Layer w0.2: U2.14@38.2,26.5 38.2,20.523 40.688,18.035 48.085,18.035 P7.16@51.18,14.94
AGND: C20.1 C132.2 C133.2 C142.2 C143.2 C152.2 C153.2 C232.2 C233.1 C234.2 C235.1 C236.2 C237.1 CL420.1 R101.2 R103.2 U2.8 | length 45.4
  Top Layer w0.2: C20.1@35.62,21.32 35.8,21.5 U2.8@35.8,26.5
  Top Layer w0.8: v3(33.5,18.3) v3@34.7,18.3 ; v3(35.016,18.3) 35.4,18.684 C20.1@35.4,20.8 ; CL420.1@36.04,4.84 C153.2@38.215,4.84 ; v1(38.26,3.46) 38.26,4.795 C153.2@38.215,4.84 ; C152.2@39.97,4.84 C153.2@38.215,4.84 ; v1(40.015,3.46) C152.2@40.015,4.795 ; v1(43.024,3.46) C143.2@43.024,4.795 ; v1(46.032,3.46) C142.2@46.032,4.795 ; C133.2@48.996,4.84 C132.2@52.005,4.84 ; v1(49.041,3.46) C133.2@49.041,4.795 ; v1(49.119,64.28) v1@49.123,64.28 ; C237.1@49.123,65.65 v1@49.123,64.28 ; C236.2@50.896,65.65 50.896,64.28 v1@49.123,64.28 ; v1(63.762,64.28) v1@63.766,64.28 ; C234.2@63.766,65.65 v1@63.766,64.28 ; C235.1@65.558,65.65 65.558,64.28 v1@63.766,64.28 ; v1(76.187,64.28) v1@76.192,64.28 ; C233.1@76.192,65.65 v1@76.192,64.28 ; C232.2@78.011,65.65 78.011,64.28 v1@76.192,64.28
  Top Layer w1: C152.2@39.97,4.84 C143.2@42.979,4.84 C142.2@45.987,4.84 C133.2@48.996,4.84
  other v1: 75.016,4.5 76.31,4.5 77.605,4.5 78.9,4.5 75,8.367 76.167,8.367 77.333,8.367 78.5,8.367 30.9,18.26 30.06,18.31 30.53,18.967 77.116,62.567 76.216,63.424 78.016,63.424 50.892,64.28 65.553,64.28 78.007,64.28
AVDD: C20.2 R98.1 R100.1 R130.2 R131.2 R140.1 R141.2 R150.2 R151.2 U2.7 | length 146.3
  Top Layer w0.2: C20.2@33.9,21.1 33.9,21.4 35.4,22.9 U2.7@35.4,26.5
  Top Layer w0.6: C20.2@33.6,21.1 33.8,20.9 v3(33.8,19.8) ; v1(42.95,18.8) 47.8,18.8 51.1,22.1 v1(51.15,22.1) ; v3(48.605,61.3) 51.327,61.3 55.227,57.4 57.3,57.4 60.4,54.3 67.227,54.3 69,52.527 R100.1@69,43.8 R98.1@69,42.1 69,40 v1(61.6,32.6)
  Top Layer w0.8: v3@45.535,64.28 R151.2@45.535,65.65 ; v1@54.39,64.31 R150.2@54.39,65.68 ; v1@60.184,64.28 R140.1@60.184,65.65 ; v1@69.14,64.28 R141.2@69.14,65.65 ; v1@72.554,64.28 R131.2@72.554,65.65 ; v1@81.65,64.28 R130.2@81.65,65.65
  Bottom Layer w0.6: v3(33.8,19.8) 35.5,19.8 36.5,18.8 v1(42.95,18.8) v1(43.74,18.8) ; v1(50.5,21.5) v1(62.15,33.15)
  Bottom Layer w0.8: v3(48.605,61.3) 48.51,61.3 v3(45.53,64.28) 45.53,64.82 46.36,65.65 80.275,65.65 v1(81.645,64.28) ; v1(54.385,64.31) 54.385,65.645 ; v1(60.179,64.28) 60.179,65.645 ; v1(69.135,64.28) 69.135,65.565 ; v1(72.549,64.28) 72.549,65.645
BOOT: CL7.1 P3.1 P4.10 R61.1 U2.3 | length 61.3
  Top Layer w0.2: P3.1@8.3,46.6 11.4,43.5 11.4,31.4 17.8,25 33.231,25 33.8,25.569 U2.3@33.8,26.5
  Top Layer w0.6: P4.10@8.31,21.81 12.57,21.81 14.61,19.77 R61.1@16.32,19.77
  Bottom Layer w0.6: P4.10@8.31,21.81 11.01,21.81 v1(16,26.8)
CFBOT: C77.2 P34.1 U2.27 | length 24.8
  Top Layer w0.2: U2.27@39.4,32.5 40.8,32.5 v3(43.6,35.3) 44.193,35.893 C77.2@45.41,35.893
  Bottom Layer w0.25: v3(43.6,35.3) 52,35.3 P34.1@52.2,35.5 43.8,35.5 v3(43.6,35.3)
CFTOP: C77.1 P34.2 U2.26 | length 19.2
  Top Layer w0.2: U2.26@39.4,32.1 42.2,32.1 43.65,33.55 45.48,33.55 C77.1@45.48,33.677 ; C77.1@45.41,33.607 C77.1@45.48,33.677 ; C77.1@45.843,34.04 C77.1@45.48,33.677
  Bottom Layer w0.2: v3(43.7,33.6) 44.1,34 53.24,34 P34.2@54.74,35.5
DVDD: C3.2 C21.2 C22.2 C23.2 C24.2 D7.1 L2.2 P32.1 P32.2 P32.3 P32.4 R24.2 R32.1 R68.2 R77.1 R98.2 R100.2 U2.15 U2.48 | length 172.6
  Top Layer w0.2: 25.49,31.18 25.77,30.9 U2.48@31.8,30.9
  Top Layer w0.6: R68.2@18.03,21.89 22.439,21.89 v1(23.229,21.1) v1@23.3,21.029 ; R77.1@18.07,19.76 R68.2@18.07,21.85 ; C24.2@19.1,72.662 18.862,72.662 16.7,70.5 16.7,36 21.3,31.4 v1(24,31.4) ; v1(23.2,31.4) v1(24,31.4) ; v1@23.3,21.1 v1(24,21.1) ; v1@24,21 v1(24,21.1) ; R32.1@25.446,17.86 25.446,20.466 ; C22.2@27.02,32.39 26.03,31.4 v1(24,31.4) ; v1(31.15,20.49) v1(30.34,20.49) 25.421,20.49 24.811,21.1 v1(24,21.1)
  Top Layer w0.8: C24.2@19.1,72.662 R24.2@19.1,75.565 ; C21.2@40,21.2 v1(40,19.9) v1(40.8,19.9) 46.6,19.9 v3(50.1,23.4) ; C23.2@56.039,42.51 P32.4@60.2,42.51 ; v3(59.9,33.2) 64.81,38.11 D7.1@64.81,42.527 66.773,42.527 ; P32.4@60.2,42.48 P32.4@60.2,42.51 ; D7.1@64.293,42.51 P32.4@60.2,42.51 ; 67.2,42.527 R100.2@67.2,43.8
  Top Layer w1: L2.2@55.619,46.88 L2.2@55.619,49.561 ; P32.4@60.2,42.51 P32.3@60.2,45.02 P32.2@60.2,47.56 P32.1@60.2,50.1
  Bottom Layer w0.6: v1@23.2,21.1 v1(23.2,31.4) ; v1@23.971,21.1 v1@23.971,31.4
  Bottom Layer w0.8: v1(30.34,20.49) v1(31.15,20.49) 31.56,20.9 36.25,20.9 37.25,19.9 v1(40,19.9) v1(40.8,19.9) ; v1(49.4,22.7) v3(59.9,33.2) v3(60.6,33.9)
FBG: C60.2 U2.30 | length 6.6
  Top Layer w0.2: U2.30@37.8,34.1 37.8,35.7 38.56,36.46 40.89,38.79 C60.2@40.89,39.45
GND: C1.2 C2.2 C3.1 C4.2 C5.2 C6.2 C9.2 C21.1 C22.1 C23.1 C24.1 C25.1 C54.1 C62.1 C70.2 C71.2 C72.2 CL3.1 CL7.2 CL8.2 CL53.1 CL54.1 CL65.1 CL66.1 E1.2 E2.2 JP10.1 JP10.3 P3.2 P3.4 P3.6 P3.8 P3.10 P3.12 P3.14 P3.16 P3.18 P3.20 P3.22 P3.24 P3.26 P4.4 P24.3 P33.1 P33.2 P33.3 P33.4 P37.1 P37.2 P37.3 P37.4 P39.1 P39.2 P39.3 P39.4 pad.0 R13.1 R14.1 R15.1 R16.1 R66.2 R101.1 R103.1 R134.1 R144.1 R154.1 R441.1 S1.2 S3.2 U2.57 Vin-.1 ZD1.2 | length 120.8
  Top Layer w0.2: C21.1@41.8,21.2 43.4,21.2
  Top Layer w0.3: v3(38.9,83.2) 38.4,83.7 38.4,87.6 38.6,87.8 R15.1@41.275,87.8 ; v3(72.6,83.6) 72.1,84.1 72.1,87.6 72.3,87.8 R14.1@74.975,87.8 ; R134.1@100,80.9 100,83.9 102.5,86.4 102.5,88.3 102.7,88.5 R13.1@105.375,88.5
  Top Layer w0.5: v1(34.5,40.9) 34.5,42.5 34.3,42.7 32.8,44.2 32.8,51.6 v1(34.9,53.7)
  Top Layer w0.6: C6.2@7.5,90.4 C9.2@7.5,98.48 ; C24.1@20.9,72.662 24.018,72.662 P24.3@24.2,72.48 ; v1(23.2,34.6) C54.1@25.216,34.6 ; v3@25.816,16.63 26.13,16.63 26.74,17.24 26.74,18.18 26.783,18.223 v3@27.416,18.223 ; R154.1@50.87,76.83 50.87,77.12 R154.1@50.91,77.16 ; v1(50.87,78.27) 50.87,77.2 R154.1@50.91,77.16 ; R154.1@50.91,76.87 R154.1@50.91,77.16 ; 64,17.2 CL65.1@64,18.7 ; R144.1@68.15,78.379 70.341,78.379 JP10.1@72.17,76.55 JP10.3@74.71,76.55
  Top Layer w0.7: CL8.2@21.723,19.61 v3(24.16,19.61) ; C62.1@42.96,39.46 C71.2@44.705,39.46 ; C3.1@53.333,44.641 53.333,43.416 C23.1@54.239,42.51
  Top Layer w0.8: v3(13.6,16.14) v3(14.64,16.14) CL7.2@14.64,17.94 ; R66.2@20.8,63 CL3.1@22.7,63 ; 21.4,63.1 v1(21.4,65.1) ; v1(21.7,32.7) C22.1@25.3,32.7
  Top Layer w1: v3(51.59,44.52) 53.264,44.52 C3.1@53.333,44.451 ; v3(86.6,5.7) 86.65,5.65 R441.1@88.16,5.65
  Bottom Layer w0.6: v3(38.9,83.2) 42.49,79.61 49.53,79.61 v1(50.87,78.27) ; v3(72.6,83.6) 72.6,81.8 70.6,79.8 70.6,78.12 JP10.1@72.17,76.55 JP10.3@74.71,76.55
  Bottom Layer w1: v4(81.8,9.4) 85.5,5.7 v3(86.6,5.7)
  other v1: 28.53,1.28 34.75,1.35 40.63,1.43 22.47,1.5 46.2,1.5 15.3,2.04 11.33,2.19 81.7,4.167 27.36,4.56 33.4,6.8 27.37,7.02 34.6,8.5 34.6,10.2 27.51,10.64 25.97,15.29 71.016,15.8 54.3,16.8 51.77,17.24 66.2,18.767 51.94,19.92 43.216,21.58 44.177,21.58 45.139,21.58 46.1,21.58 42.64,22.58 47.7,22.967 31.1,23.82 25.24,23.87 27.317,23.89 29.533,23.89 48.016,24.2 62.2,24.6 56.1,25 59.9,25 66.1,26.6 70.6,26.9 67.8,27.3 71.816,28 3.7,29 71.8,31.2 1.35,32.03 1.45,32.023 22.7,32.7 23.7,32.7 56.3,32.767 57.616,33.4 1.35,33.738 71.2,34.4 24,34.6 46.77,40.01 46.78,40.94 52.83,41.43 47.11,42.662 52.69,42.67 51.61,42.78 36.4,44 37.5,44.4 46.81,44.914 36,46.3 1.35,46.831 46.81,47.166 46.81,49.418 46.81,51.67 1.35,53.554 21.8,53.7 49.72,54.29 46.92,54.38 18,56.7 24.6,57.767 1.35,58.462 20.8,58.767 56.3,61.167 21.016,61.8 1.35,63.369 43.88,63.567 39.12,63.9 40.31,63.93 18,65.1 25.5,65.1 1.35,68.277 38.85,68.93 69.25,68.93 71.07,68.93 53.74,69.21 43.78,69.63 46.04,69.67 53.63,70.88 43.91,71.48 15.5,72 16.94,72.567 78.616,72.56 38.85,72.625 57.42,72.83 1.35,73.185 47.22,73.59 57.39,74.24 53.71,75.1 64.616,75.34 17.31,75.56 81.64,75.567 38.85,76.32 78.49,76.62 81.79,77.8 56.4,77.87 86.5,78.02 1.35,78.092 53.49,78.34 12.616,78.4 25.3,78.567 17.416,78.6 21.5,79.1 78.48,80.27 81.8,80.3 86.36,80.4 14.216,80.7 18.416,81.2 22.416,81.3 93.4,81.4
  other v2: 8.016,11.1 5.416,13.2 10.416,14.7 1.616,16.9 11.9,17.567 15.016,21.7 4.9,35.8 19.5,40.967 1.3,41.2 5.416,41.7 22.8,41.8 22.616,45.8 25.016,46.2 19.1,46.567 18.5,50.5 25,50.9 40,85.367 41.608,85.367 43.216,85.367 73.616,85.367 75.308,85.367 77,85.367 8.6,86.767 43.216,86.812 77,86.845 5.416,87 43.216,88.256 77,88.322 5.416,89.314 43.216,89.7 77,89.8 39.8,90.3 73.5,90.367 39.8,91.8 5.416,91.86 73.5,91.884 39.8,93.3 73.5,93.4 5.416,94.367 7.158,94.367 8.9,94.367 5.416,96.953 5.416,99.5 9.3,100.167 7.216,100.8
  other v3: 54.05,1.567 62.3,1.567 70.55,1.567 78.8,1.567 25.93,16.41 27.32,18.55 23.16,19.61 21.5,24.06 3.27,24.97 40.01,35.06 40.89,36.05 57.9,39.6 54.4,39.7 61.6,39.8 33,44.4 62.7,45.3 67,45.767 62.7,47.8 1.45,48.746 62.7,51.8 67.016,51.8 54.9,55 35.8,57.5 40.1,59.6 35.5,72.8 12.4,75.9 101.8,77 103.6,77 101.8,78.2 103.6,78.2 101.8,79.4 103.6,79.4 9.5,80.2 101.8,80.6 103.6,80.6 101.8,81.8 103.6,81.8 101.8,83 103.6,83 101.8,84.2 103.6,84.2
  other v4: 81.3,14.1 81.5,20.9 81.3,27.6 81.9,35.367 84.2,35.367 86.5,35.367 81.87,40.46 86.6,40.7 82.2,44.2 86.6,46.5 82,49 86.8,54 82,55.9 86.6,59.6 81.9,60.2 83.9,63.8 88,67 83.5,69.1 86.6,70.9 90.9,71.5 97.416,74.3
  other v5: 33.6,28.31 34.93,28.31 36.26,28.31 37.59,28.31 33.6,29.64 34.93,29.64 36.26,29.64 37.59,29.64 33.6,30.97 34.93,30.97 36.26,30.97 37.59,30.97 33.6,32.3 34.93,32.3 36.26,32.3 37.59,32.3
GPIO2: P35.2 U2.19 | length 32.9
  Top Layer w0.2: U2.19@39.4,29.3 41.64,29.3 44.13,26.81 44.9,26.81 62.31,26.81 64.6,29.1 68.34,29.1 P35.2@69.74,30.5
GPIO3: P35.1 U2.20 | length 30.1
  Top Layer w0.2: U2.20@39.4,29.7 41.95,29.7 44.35,27.3 61.9,27.3 65.1,30.5 P35.1@67.2,30.5
GPIO16: JP6.1 U2.17 | length 21
  Top Layer w0.2: U2.17@39.4,28.5 40.9,28.5 43.6,25.8 43.97,25.8 52.3,25.8 53.4,24.7 53.4,21.3 JP6.1@54.8,19.9
GPIO17: JP6.2 U2.18 | length 19
  Top Layer w0.2: U2.18@39.4,28.9 41.25,28.9 43.85,26.3 44.87,26.3 52.6,26.3 54.8,24.1 JP6.2@54.8,22.64 JP6.2@54.8,22.44
GPIO30: P3.25 U2.49 | length 62.5
  Top Layer w0.2: P3.25@8.3,77.08 16,69.38 16,35.731 21.231,30.5 U2.49@31.8,30.5
GPIO31: P3.23 U2.50 | length 60.5
  Top Layer w0.2: P3.23@8.3,74.54 15.6,67.24 15.6,35.566 21.066,30.1 U2.50@31.8,30.1
GPIO32: P3.21 U2.51 | length 58.4
  Top Layer w0.2: P3.21@8.3,72 15.2,65.1 15.2,35.4 20.9,29.7 U2.51@31.8,29.7
GPIO36: P3.13 U2.54 | length 50.5
  Top Layer w0.2: P3.13@8.3,61.84 14,56.14 14,33.61 19.11,28.5 U2.54@31.8,28.5
GPIO37: P3.11 U2.55 | length 48.5
  Top Layer w0.2: P3.11@8.3,59.3 13.6,54 13.6,33.4 18.9,28.1 U2.55@31.8,28.1
HO_U: R5.1 U2.44 | length 55.8
  Top Layer w0.2: R5.1@24.016,84.015 24.016,81.819 26.6,79.234 26.6,42 v3(26.1,41.5) ; v3(26.2,38.6) 30.43,34.37 30.43,33.086 31.016,32.5 U2.44@31.8,32.5
  Bottom Layer w0.2: v3(26.1,41.5) 26.4,41.2 26.2,41 v3(26.2,38.6)
HO_V: R3.1 U2.40 | length 66.4
  Top Layer w0.2: v3(28.8,41.4) 28.71,41.49 28.71,73.076 37.734,82.1 46.7,82.1 R3.1@49,84.4 ; v3(29.9,38.5) 30.48,38.5 33.8,35.18 U2.40@33.8,34.1
  Bottom Layer w0.2: v3(28.8,41.4) 29.9,40.3 v3(29.9,38.5)
HO_W: R1.1 U2.36 | length 96.4
  Top Layer w0.2: v1(31.3,42.3) 30.81,42.79 30.81,72.71 38.4,80.3 56.6,80.3 57.9,81.6 69.2,81.6 70.3,82.7 80.2,82.7 R1.1@81.9,84.4 ; v1(33.69,38.55) 35.4,36.84 U2.36@35.4,34.1
  Bottom Layer w0.2: v1(31.3,42.3) 31.3,40.94 v1(33.69,38.55)
IU+: C153.1 P7.5 R157.2 | length 115.3
  Top Layer w0.4: P7.5@38.48,12.4 38.1,12.02 38.1,6.755 C153.1@38.215,6.64 42.275,10.7 69.6,10.7 73.04,14.14 73.04,54.5 68.94,58.6 56.3,58.6 51.68,63.22 48.57,63.22 47.329,64.461 R157.2@47.329,65.65
IU-: C152.1 P7.7 R156.2 | length 109.4
  Top Layer w0.4: C152.1@39.97,6.64 v1(41.03,7.7) 43.33,10 69.805,10 73.68,13.875 73.68,55.16 69.54,59.3 56.667,59.3 52.712,63.255 R156.2@52.712,65.65
  Bottom Layer w0.4: P7.7@41.02,12.4 41.03,12.39 v1(41.03,7.7)
IV+: C143.1 P7.9 R147.2 | length 98.6
  Top Layer w0.4: C143.1@42.979,6.64 v1(44.1,7.761) 45.639,9.3 70.148,9.3 74.32,13.472 74.32,55.82 69.2,60.94 65.26,60.94 61.975,64.225 R147.2@61.975,65.65
  Bottom Layer w0.4: P7.9@43.56,12.4 43.56,8.301 v1(44.1,7.761)
IV-: C142.1 P7.11 R146.2 | length 92.3
  Top Layer w0.4: C142.1@45.987,6.64 v1(47.147,7.8) 47.987,8.64 70.393,8.64 74.96,13.207 74.96,56.48 67.349,64.091 R146.2@67.349,65.65
  Bottom Layer w0.4: P7.11@46.1,12.4 46.1,8.847 v1(47.147,7.8)
IW+: C133.1 P7.13 R194.2 | length 88
  Top Layer w0.6: C133.1@48.996,6.64 48.996,6.896 v1@50,7.9 ; v1(50,7.8) 70.6,7.8 75.7,12.9 75.7,57.21 74.373,58.537 R194.2@74.373,65.65
  Bottom Layer w0.6: P7.13@48.64,12.4 48.64,9.16 v1(50,7.8)
IW-: C132.1 P7.15 R136.2 | length 92.7
  Top Layer w0.6: C132.1@52.005,6.64 v1(53.2,6.64) 78.54,6.64 79.831,7.931 R136.2@79.831,65.65
  Bottom Layer w0.4: P7.15@51.18,12.4 51.18,8.66 v1(53.2,6.64)
LO_U: R11.1 U2.42 | length 53.2
  Top Layer w0.2: R11.1@28.81,84 27.9,83.09 27.9,38.4 31.45,34.85 32.84,34.85 33,34.69 U2.42@33,34.1
LO_V: R9.1 U2.38 | length 76.9
  Top Layer w0.2: U2.38@34.6,34.1 34.6,35.69 31.7,38.59 31.7,40.7 30,42.4 30,72.8 38.1,80.9 56.1,80.9 57.4,82.2 59.816,82.2 R9.1@61.616,84
LO_W: R7.1 U2.34 | length 103.8
  Top Layer w0.2: U2.34@36.2,34.1 36.2,37.936 33.5,40.636 33.5,42.1 32,43.6 32,72.44 38.96,79.4 57.1,79.4 58.4,80.7 69.8,80.7 70.6,81.5 88.4,81.5 R7.1@90.9,84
